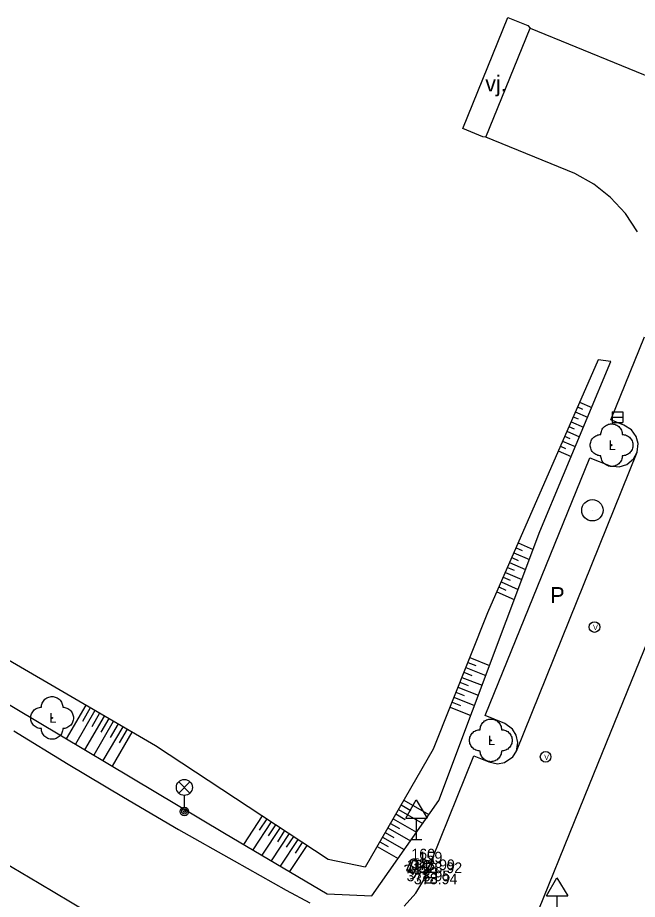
# Model space of a CAD drawing. Extents: x -836568 to -836015, y -1070547 to -1070212.
# Drawn here: x -836423.06 to -836394, y -1070381.44 to -1070340.13 of the extents above; entities that cross this region are included whole.
import ezdxf

# ---------------------------------------------------------------- set-up
doc = ezdxf.new("R2010")
doc.units = 0
for name, color, linetype in [('BodPole_mer', 7, 'Continuous'), ('BodPole_popis', 7, 'Continuous'), ('Doprava_body', 7, 'Continuous'), ('Doprava_hranice', 7, 'Continuous'), ('Doprava_kody', 7, 'Continuous'), ('PovrZnIS_body', 7, 'Continuous'), ('PovrZnIS_hranice', 7, 'Continuous'), ('PovrZnIS_kody', 7, 'Continuous'), ('Rusene_prvky', 7, 'Continuous'), ('Vyskopis_linie', 7, 'Continuous'), ('Zelen_body', 7, 'Continuous')]:
    doc.layers.add(name, color=color, linetype=linetype)

msp = doc.modelspace()

# ---------------------------------------------------------------- linework, layer by layer
at = {"layer": 'BodPole_mer'}
for p, q in [((-836400.07, -1070340.13), (-836400.07, -1070340.13)), ((-836399.14, -1070340.5), (-836399.14, -1070340.5)), ((-836399.02, -1070340.62), (-836399.02, -1070340.62)), ((-836402.18, -1070345.33), (-836402.18, -1070345.33)), ((-836401.25, -1070345.72), (-836401.25, -1070345.72)), ((-836401.11, -1070345.73), (-836401.11, -1070345.73)), ((-836396.94, -1070347.44), (-836396.94, -1070347.44)), ((-836396.04, -1070347.93), (-836396.04, -1070347.93)), ((-836395.26, -1070348.55), (-836395.26, -1070348.55)), ((-836394.55, -1070349.31), (-836394.55, -1070349.31)), ((-836395.84, -1070356.16), (-836395.84, -1070356.16)), ((-836395.25, -1070356.24), (-836395.25, -1070356.24)), ((-836395.25, -1070358.98), (-836395.25, -1070358.98)), ((-836394.93, -1070358.85), (-836394.93, -1070358.85)), ((-836394.63, -1070359.22), (-836394.63, -1070359.22)), ((-836394.27, -1070359.44), (-836394.27, -1070359.44)), ((-836394.05, -1070359.75), (-836394.05, -1070359.75)), ((-836395.21, -1070360.16), (-836395.21, -1070360.16)), ((-836394.01, -1070360.49), (-836394.01, -1070360.49)), ((-836396.23, -1070360.75), (-836396.23, -1070360.75)), ((-836394.49, -1070361.06), (-836394.49, -1070361.06)), ((-836394.18, -1070360.8), (-836394.18, -1070360.8)), ((-836395.27, -1070361.13), (-836395.27, -1070361.13)), ((-836394.85, -1070361.17), (-836394.85, -1070361.17)), ((-836396.11, -1070363.21), (-836396.11, -1070363.21)), ((-836398.57, -1070364.21), (-836398.57, -1070364.21)), ((-836401.02, -1070368.01), (-836401.02, -1070368.01)), ((-836396.01, -1070368.68), (-836396.01, -1070368.68)), ((-836421.44, -1070372.94), (-836421.44, -1070372.94)), ((-836401.14, -1070372.82), (-836401.14, -1070372.82)), ((-836400.21, -1070373.2), (-836400.21, -1070373.2)), ((-836399.86, -1070373.46), (-836399.86, -1070373.46)), ((-836399.68, -1070373.74), (-836399.68, -1070373.74)), ((-836416.6, -1070374.24), (-836416.6, -1070374.24)), ((-836400.87, -1070373.99), (-836400.87, -1070373.99)), ((-836399.6, -1070374.09), (-836399.6, -1070374.09)), ((-836403.57, -1070374.4), (-836403.57, -1070374.4)), ((-836401.66, -1070374.72), (-836401.66, -1070374.72)), ((-836399.66, -1070374.49), (-836399.66, -1070374.49)), ((-836420.69, -1070375.11), (-836420.69, -1070375.11)), ((-836400.97, -1070374.99), (-836400.97, -1070374.99)), ((-836400.56, -1070375.09), (-836400.56, -1070375.09)), ((-836400.23, -1070375.03), (-836400.23, -1070375.03)), ((-836399.84, -1070374.77), (-836399.84, -1070374.77)), ((-836398.3, -1070374.76), (-836398.3, -1070374.76)), ((-836396.26, -1070376.08), (-836396.26, -1070376.08)), ((-836418.1, -1070376.65), (-836418.1, -1070376.65)), ((-836403.31, -1070376.81), (-836403.31, -1070376.81)), ((-836415.24, -1070377.32), (-836415.24, -1070377.32)), ((-836415.51, -1070378.17), (-836415.51, -1070378.17)), ((-836413.35, -1070378.34), (-836413.35, -1070378.34)), ((-836404.36, -1070378.63), (-836404.36, -1070378.63)), ((-836412.9, -1070379.64), (-836412.9, -1070379.64)), ((-836408.49, -1070379.57), (-836408.49, -1070379.57)), ((-836404.6, -1070379.57), (-836404.6, -1070379.57)), ((-836406.76, -1070379.93), (-836406.76, -1070379.93)), ((-836404.82, -1070380.09), (-836404.82, -1070380.09)), ((-836404.26, -1070379.71), (-836404.26, -1070379.71)), ((-836404.48, -1070380.23), (-836404.48, -1070380.23)), ((-836403.68, -1070380.41), (-836403.68, -1070380.41)), ((-836422.05, -1070380.7), (-836422.05, -1070380.7)), ((-836404.01, -1070380.52), (-836404.01, -1070380.52)), ((-836410.46, -1070381.01), (-836410.46, -1070381.01)), ((-836408.55, -1070381.18), (-836408.55, -1070381.18)), ((-836406.45, -1070381.27), (-836406.45, -1070381.27)), ((-836404.38, -1070381.15), (-836404.38, -1070381.15))]:
    msp.add_line(p, q, dxfattribs=at)
at = {"layer": 'Doprava_body'}
for p, q in [((-836404.86, -1070377.63), (-836404.379, -1070376.776)), ((-836404.379, -1070376.776), (-836403.86, -1070377.63)), ((-836404.86, -1070377.63), (-836403.86, -1070377.63)), ((-836404.36, -1070378.63), (-836404.36, -1070377.63)), ((-836404.61, -1070378.63), (-836404.11, -1070378.63)), ((-836398.26, -1070381.28), (-836397.779, -1070380.426)), ((-836397.779, -1070380.426), (-836397.26, -1070381.28)), ((-836398.26, -1070381.28), (-836397.26, -1070381.28)), ((-836397.76, -1070382.28), (-836397.76, -1070381.28))]:
    msp.add_line(p, q, dxfattribs=at)
at = {"layer": 'Doprava_hranice'}
msp.add_line((-836399.66, -1070374.49), (-836394.01, -1070360.49), dxfattribs=at)
for points in [[(-836401.11, -1070345.73), (-836401.25, -1070345.72), (-836402.18, -1070345.33), (-836400.07, -1070340.13), (-836399.14, -1070340.5), (-836399.02, -1070340.62)], [(-836393.99, -1070350.16), (-836394.55, -1070349.31), (-836395.26, -1070348.55), (-836396.04, -1070347.93), (-836396.94, -1070347.44), (-836401.11, -1070345.73), (-836399.02, -1070340.62), (-836392.61, -1070343.24)], [(-836395.27, -1070361.13), (-836394.85, -1070361.17), (-836394.49, -1070361.06), (-836394.18, -1070360.8), (-836394.01, -1070360.49), (-836393.96, -1070360.08), (-836394.05, -1070359.75), (-836394.27, -1070359.44), (-836394.63, -1070359.22), (-836395.25, -1070358.98), (-836393.66, -1070355.09)], [(-836388.58, -1070357.21), (-836396.26, -1070376.08), (-836399.34, -1070383.66)], [(-836404.94, -1070381.76), (-836404.38, -1070381.15), (-836404.01, -1070380.52), (-836401.66, -1070374.72), (-836400.97, -1070374.99), (-836400.56, -1070375.09), (-836400.23, -1070375.03), (-836399.84, -1070374.77), (-836399.66, -1070374.49), (-836399.6, -1070374.09), (-836399.68, -1070373.74), (-836399.86, -1070373.46), (-836400.21, -1070373.2), (-836401.14, -1070372.82), (-836396.23, -1070360.75), (-836395.27, -1070361.13)], [(-836423.24, -1070373.54), (-836420.69, -1070375.11), (-836418.1, -1070376.65), (-836415.51, -1070378.17), (-836412.9, -1070379.64), (-836410.46, -1070381.01), (-836409.36, -1070381.6)], [(-836399.24, -1070392.97), (-836400.17, -1070392.53), (-836400.46, -1070392.39), (-836403.15, -1070391.04), (-836405.83, -1070389.69), (-836408.48, -1070388.3), (-836410.81, -1070387.09), (-836411.14, -1070386.91), (-836411.71, -1070386.58), (-836413.77, -1070385.45), (-836416.56, -1070383.89), (-836418.13, -1070383), (-836419.85, -1070382.01), (-836422.05, -1070380.7), (-836424.17, -1070379.44)]]:
    msp.add_lwpolyline(points, dxfattribs=at)
at = {"layer": 'PovrZnIS_body'}
for p, q in [((-836395.18, -1070358.6), (-836394.68, -1070358.6)), ((-836395.18, -1070358.6), (-836395.18, -1070359.1)), ((-836394.68, -1070358.6), (-836394.68, -1070359.1)), ((-836395.18, -1070358.85), (-836394.68, -1070358.85)), ((-836395.18, -1070359.1), (-836394.68, -1070359.1)), ((-836415.505, -1070376.46), (-836414.975, -1070375.93)), ((-836415.505, -1070375.93), (-836414.975, -1070376.46)), ((-836415.24, -1070377.12), (-836415.24, -1070376.57)), ((-836403.93, -1070380.16), (-836403.43, -1070380.16)), ((-836403.93, -1070380.16), (-836403.93, -1070380.66)), ((-836403.93, -1070380.41), (-836403.43, -1070380.41)), ((-836403.43, -1070380.16), (-836403.43, -1070380.66)), ((-836403.93, -1070380.66), (-836403.43, -1070380.66))]:
    msp.add_line(p, q, dxfattribs=at)
for centre, radius in [((-836396.11, -1070363.21), 0.5), ((-836396.01, -1070368.68), 0.25), ((-836398.3, -1070374.76), 0.25)]:
    msp.add_circle(centre, radius, dxfattribs=at)
for centre, major_axis in [((-836415.24, -1070376.195), (0.375, 0)), ((-836415.24, -1070377.32), (0.2, 0)), ((-836415.236, -1070377.32), (0.125, 0)), ((-836415.236, -1070377.32), (0.05, 0))]:
    msp.add_ellipse(centre, major_axis=major_axis, ratio=0.999998, dxfattribs=at)
at = {"layer": 'PovrZnIS_hranice'}
msp.add_lwpolyline([(-836404.48, -1070380.23), (-836404.26, -1070379.71), (-836404.6, -1070379.57), (-836404.82, -1070380.09), (-836404.48, -1070380.23)], dxfattribs=at)
at = {"layer": 'PovrZnIS_kody'}
for centre, radius, start, end in [((-836404.735, -1070380.146), 0.315, 53.2248, 126.7372), ((-836404.361, -1070379.644), 0.313, 233.1301, 306.8699)]:
    msp.add_arc(centre, radius, start, end, dxfattribs=at)
at = {"layer": 'Rusene_prvky'}
for p, q in [((-836404.72, -1070380.15), (-836404.51, -1070379.61)), ((-836404.28, -1070379.7), (-836404.51, -1070379.61)), ((-836404.51, -1070379.61), (-836404.51, -1070379.61)), ((-836404.49, -1070380.24), (-836404.28, -1070379.7)), ((-836404.28, -1070379.7), (-836404.28, -1070379.7)), ((-836404.72, -1070380.15), (-836404.49, -1070380.24)), ((-836404.72, -1070380.15), (-836404.72, -1070380.15)), ((-836404.49, -1070380.24), (-836404.49, -1070380.24))]:
    msp.add_line(p, q, dxfattribs=at)
for centre, radius, start, end in [((-836404.302, -1070379.67), 0.313, 278.1301, 351.8699), ((-836404.677, -1070380.172), 0.315, 278.2248, 351.7372)]:
    msp.add_arc(centre, radius, start, end, dxfattribs=at)
at = {"layer": 'Vyskopis_linie'}
for p, q in [((-836396.71, -1070358.14), (-836396.14, -1070358.39)), ((-836396.91, -1070358.6), (-836396.34, -1070358.85)), ((-836396.81, -1070358.37), (-836396.58, -1070358.47)), ((-836397.01, -1070358.83), (-836396.77, -1070358.93)), ((-836397.21, -1070359.29), (-836396.97, -1070359.39)), ((-836397.11, -1070359.06), (-836396.53, -1070359.31)), ((-836397.41, -1070359.74), (-836397.17, -1070359.85)), ((-836397.31, -1070359.51), (-836396.72, -1070359.77)), ((-836397.61, -1070360.2), (-836397.37, -1070360.31)), ((-836397.51, -1070359.97), (-836396.91, -1070360.23)), ((-836397.71, -1070360.43), (-836397.11, -1070360.69)), ((-836399.59, -1070364.74), (-836398.89, -1070365.05)), ((-836399.79, -1070365.2), (-836399.06, -1070365.52)), ((-836399.69, -1070364.97), (-836399.4, -1070365.1)), ((-836399.89, -1070365.43), (-836399.59, -1070365.56)), ((-836400.09, -1070365.89), (-836399.78, -1070366.02)), ((-836399.99, -1070365.66), (-836399.24, -1070365.99)), ((-836400.29, -1070366.35), (-836399.97, -1070366.49)), ((-836400.19, -1070366.12), (-836399.42, -1070366.46)), ((-836400.49, -1070366.8), (-836400.16, -1070366.95)), ((-836400.39, -1070366.57), (-836399.59, -1070366.93)), ((-836400.59, -1070367.03), (-836399.77, -1070367.39)), ((-836401.86, -1070370.11), (-836400.93, -1070370.48)), ((-836402.04, -1070370.57), (-836401.1, -1070370.95)), ((-836401.95, -1070370.34), (-836401.57, -1070370.49)), ((-836402.13, -1070370.8), (-836401.76, -1070370.95)), ((-836402.32, -1070371.27), (-836401.94, -1070371.42)), ((-836402.23, -1070371.04), (-836401.28, -1070371.41)), ((-836402.51, -1070371.73), (-836402.12, -1070371.89)), ((-836402.41, -1070371.5), (-836401.46, -1070371.88)), ((-836402.69, -1070372.2), (-836402.3, -1070372.35)), ((-836402.6, -1070371.96), (-836401.63, -1070372.35)), ((-836419.86, -1070372.34), (-836420.78, -1070373.92)), ((-836419.43, -1070372.59), (-836420.35, -1070374.17)), ((-836419.65, -1070372.47), (-836420.01, -1070373.1)), ((-836402.78, -1070372.43), (-836401.81, -1070372.82)), ((-836419, -1070372.85), (-836419.92, -1070374.43)), ((-836419.21, -1070372.72), (-836419.58, -1070373.35)), ((-836418.78, -1070372.97), (-836419.15, -1070373.6)), ((-836418.57, -1070373.1), (-836419.49, -1070374.68)), ((-836418.13, -1070373.35), (-836419.06, -1070374.94)), ((-836418.35, -1070373.22), (-836418.72, -1070373.86)), ((-836417.92, -1070373.47), (-836418.29, -1070374.11)), ((-836417.7, -1070373.6), (-836418.63, -1070375.2)), ((-836404.95, -1070376.79), (-836403.77, -1070377.47)), ((-836405.08, -1070377.01), (-836404.62, -1070377.27)), ((-836411.59, -1070377.53), (-836412.46, -1070378.87)), ((-836405.32, -1070377.44), (-836404.89, -1070377.7)), ((-836405.2, -1070377.23), (-836404.06, -1070377.88)), ((-836411.17, -1070377.81), (-836412.03, -1070379.12)), ((-836411.38, -1070377.67), (-836411.73, -1070378.2)), ((-836410.96, -1070377.95), (-836411.31, -1070378.47)), ((-836405.57, -1070377.88), (-836405.15, -1070378.12)), ((-836405.45, -1070377.66), (-836404.35, -1070378.29)), ((-836410.75, -1070378.08), (-836411.6, -1070379.37)), ((-836410.33, -1070378.36), (-836411.17, -1070379.63)), ((-836410.54, -1070378.22), (-836410.88, -1070378.74)), ((-836405.82, -1070378.31), (-836405.42, -1070378.54)), ((-836405.7, -1070378.09), (-836404.64, -1070378.7)), ((-836409.92, -1070378.63), (-836410.74, -1070379.88)), ((-836410.13, -1070378.5), (-836410.46, -1070379)), ((-836409.71, -1070378.77), (-836410.04, -1070379.27)), ((-836406.07, -1070378.74), (-836405.68, -1070378.97)), ((-836405.95, -1070378.52), (-836404.93, -1070379.11)), ((-836409.5, -1070378.91), (-836410.31, -1070380.14)), ((-836406.2, -1070378.96), (-836405.22, -1070379.52))]:
    msp.add_line(p, q, dxfattribs=at)
for points in [[(-836434.23, -1070354.27), (-836438.23, -1070358.57), (-836440.17, -1070361.78), (-836433.66, -1070365.96), (-836425.36, -1070371.19), (-836413.35, -1070378.34), (-836408.55, -1070381.18), (-836406.45, -1070381.27), (-836403.31, -1070376.81), (-836398.57, -1070364.21), (-836395.25, -1070356.24), (-836395.84, -1070356.16)], [(-836395.84, -1070356.16), (-836401.02, -1070368.01), (-836403.57, -1070374.4), (-836406.76, -1070379.93), (-836408.49, -1070379.57), (-836416.6, -1070374.24), (-836425.3, -1070369.18), (-836431.77, -1070364.85), (-836437.84, -1070361.03), (-836434.23, -1070354.27)]]:
    msp.add_lwpolyline(points, dxfattribs=at)
at = {"layer": 'Zelen_body'}
for p, q in [((-836395.21, -1070360.16), (-836395.21, -1070360.16)), ((-836421.44, -1070372.94), (-836421.44, -1070372.94)), ((-836400.87, -1070373.99), (-836400.87, -1070373.99))]:
    msp.add_line(p, q, dxfattribs=at)
for points in [[(-836395.71, -1070359.66), (-836395.708, -1070359.612), (-836395.7, -1070359.563), (-836395.688, -1070359.513), (-836395.67, -1070359.464), (-836395.646, -1070359.415), (-836395.617, -1070359.369), (-836395.583, -1070359.326), (-836395.544, -1070359.287), (-836395.501, -1070359.253), (-836395.455, -1070359.224), (-836395.406, -1070359.2), (-836395.357, -1070359.182), (-836395.307, -1070359.17), (-836395.258, -1070359.162), (-836395.21, -1070359.16), (-836395.162, -1070359.162), (-836395.113, -1070359.17), (-836395.063, -1070359.182), (-836395.014, -1070359.2), (-836394.965, -1070359.224), (-836394.919, -1070359.253), (-836394.876, -1070359.287), (-836394.837, -1070359.326), (-836394.803, -1070359.369), (-836394.774, -1070359.415), (-836394.75, -1070359.464), (-836394.732, -1070359.513), (-836394.72, -1070359.563), (-836394.712, -1070359.612), (-836394.71, -1070359.66)], [(-836395.71, -1070360.66), (-836395.758, -1070360.658), (-836395.807, -1070360.65), (-836395.857, -1070360.638), (-836395.906, -1070360.62), (-836395.955, -1070360.596), (-836396.001, -1070360.567), (-836396.044, -1070360.533), (-836396.083, -1070360.494), (-836396.117, -1070360.451), (-836396.146, -1070360.405), (-836396.17, -1070360.356), (-836396.188, -1070360.307), (-836396.2, -1070360.257), (-836396.208, -1070360.208), (-836396.21, -1070360.16), (-836396.208, -1070360.112), (-836396.2, -1070360.063), (-836396.188, -1070360.013), (-836396.17, -1070359.964), (-836396.146, -1070359.915), (-836396.117, -1070359.869), (-836396.083, -1070359.826), (-836396.044, -1070359.787), (-836396.001, -1070359.753), (-836395.955, -1070359.724), (-836395.906, -1070359.7), (-836395.857, -1070359.682), (-836395.807, -1070359.67), (-836395.758, -1070359.662), (-836395.71, -1070359.66)], [(-836394.71, -1070359.66), (-836394.662, -1070359.662), (-836394.613, -1070359.67), (-836394.563, -1070359.682), (-836394.514, -1070359.7), (-836394.465, -1070359.724), (-836394.419, -1070359.753), (-836394.376, -1070359.787), (-836394.337, -1070359.826), (-836394.303, -1070359.869), (-836394.274, -1070359.915), (-836394.25, -1070359.964), (-836394.232, -1070360.013), (-836394.22, -1070360.063), (-836394.212, -1070360.112), (-836394.21, -1070360.16), (-836394.212, -1070360.208), (-836394.22, -1070360.257), (-836394.232, -1070360.307), (-836394.25, -1070360.356), (-836394.274, -1070360.405), (-836394.303, -1070360.451), (-836394.337, -1070360.494), (-836394.376, -1070360.533), (-836394.419, -1070360.567), (-836394.465, -1070360.596), (-836394.514, -1070360.62), (-836394.563, -1070360.638), (-836394.613, -1070360.65), (-836394.662, -1070360.658), (-836394.71, -1070360.66)], [(-836394.71, -1070360.66), (-836394.712, -1070360.708), (-836394.72, -1070360.757), (-836394.732, -1070360.807), (-836394.75, -1070360.856), (-836394.774, -1070360.905), (-836394.803, -1070360.951), (-836394.837, -1070360.994), (-836394.876, -1070361.033), (-836394.919, -1070361.067), (-836394.965, -1070361.096), (-836395.014, -1070361.12), (-836395.063, -1070361.138), (-836395.113, -1070361.15), (-836395.162, -1070361.158), (-836395.21, -1070361.16), (-836395.258, -1070361.158), (-836395.307, -1070361.15), (-836395.357, -1070361.138), (-836395.406, -1070361.12), (-836395.455, -1070361.096), (-836395.501, -1070361.067), (-836395.544, -1070361.033), (-836395.583, -1070360.994), (-836395.617, -1070360.951), (-836395.646, -1070360.905), (-836395.67, -1070360.856), (-836395.688, -1070360.807), (-836395.7, -1070360.757), (-836395.708, -1070360.708), (-836395.71, -1070360.66)], [(-836421.94, -1070372.44), (-836421.938, -1070372.392), (-836421.93, -1070372.343), (-836421.918, -1070372.293), (-836421.9, -1070372.244), (-836421.876, -1070372.195), (-836421.847, -1070372.149), (-836421.813, -1070372.106), (-836421.774, -1070372.067), (-836421.731, -1070372.033), (-836421.685, -1070372.004), (-836421.636, -1070371.98), (-836421.587, -1070371.962), (-836421.537, -1070371.95), (-836421.488, -1070371.942), (-836421.44, -1070371.94), (-836421.392, -1070371.942), (-836421.343, -1070371.95), (-836421.293, -1070371.962), (-836421.244, -1070371.98), (-836421.195, -1070372.004), (-836421.149, -1070372.033), (-836421.106, -1070372.067), (-836421.067, -1070372.106), (-836421.033, -1070372.149), (-836421.004, -1070372.195), (-836420.98, -1070372.244), (-836420.962, -1070372.293), (-836420.95, -1070372.343), (-836420.942, -1070372.392), (-836420.94, -1070372.44)], [(-836421.94, -1070373.44), (-836421.988, -1070373.438), (-836422.037, -1070373.43), (-836422.087, -1070373.418), (-836422.136, -1070373.4), (-836422.185, -1070373.376), (-836422.231, -1070373.347), (-836422.274, -1070373.313), (-836422.313, -1070373.274), (-836422.347, -1070373.231), (-836422.376, -1070373.185), (-836422.4, -1070373.136), (-836422.418, -1070373.087), (-836422.43, -1070373.037), (-836422.438, -1070372.988), (-836422.44, -1070372.94), (-836422.438, -1070372.892), (-836422.43, -1070372.843), (-836422.418, -1070372.793), (-836422.4, -1070372.744), (-836422.376, -1070372.695), (-836422.347, -1070372.649), (-836422.313, -1070372.606), (-836422.274, -1070372.567), (-836422.231, -1070372.533), (-836422.185, -1070372.504), (-836422.136, -1070372.48), (-836422.087, -1070372.462), (-836422.037, -1070372.45), (-836421.988, -1070372.442), (-836421.94, -1070372.44)], [(-836420.94, -1070372.44), (-836420.892, -1070372.442), (-836420.843, -1070372.45), (-836420.793, -1070372.462), (-836420.744, -1070372.48), (-836420.695, -1070372.504), (-836420.649, -1070372.533), (-836420.606, -1070372.567), (-836420.567, -1070372.606), (-836420.533, -1070372.649), (-836420.504, -1070372.695), (-836420.48, -1070372.744), (-836420.462, -1070372.793), (-836420.45, -1070372.843), (-836420.442, -1070372.892), (-836420.44, -1070372.94), (-836420.442, -1070372.988), (-836420.45, -1070373.037), (-836420.462, -1070373.087), (-836420.48, -1070373.136), (-836420.504, -1070373.185), (-836420.533, -1070373.231), (-836420.567, -1070373.274), (-836420.606, -1070373.313), (-836420.649, -1070373.347), (-836420.695, -1070373.376), (-836420.744, -1070373.4), (-836420.793, -1070373.418), (-836420.843, -1070373.43), (-836420.892, -1070373.438), (-836420.94, -1070373.44)], [(-836401.37, -1070373.49), (-836401.368, -1070373.442), (-836401.36, -1070373.393), (-836401.348, -1070373.343), (-836401.33, -1070373.294), (-836401.306, -1070373.245), (-836401.277, -1070373.199), (-836401.243, -1070373.156), (-836401.204, -1070373.117), (-836401.161, -1070373.083), (-836401.115, -1070373.054), (-836401.066, -1070373.03), (-836401.017, -1070373.012), (-836400.967, -1070373), (-836400.918, -1070372.992), (-836400.87, -1070372.99), (-836400.822, -1070372.992), (-836400.773, -1070373), (-836400.723, -1070373.012), (-836400.674, -1070373.03), (-836400.625, -1070373.054), (-836400.579, -1070373.083), (-836400.536, -1070373.117), (-836400.497, -1070373.156), (-836400.463, -1070373.199), (-836400.434, -1070373.245), (-836400.41, -1070373.294), (-836400.392, -1070373.343), (-836400.38, -1070373.393), (-836400.372, -1070373.442), (-836400.37, -1070373.49)], [(-836420.94, -1070373.44), (-836420.942, -1070373.488), (-836420.95, -1070373.537), (-836420.962, -1070373.587), (-836420.98, -1070373.636), (-836421.004, -1070373.685), (-836421.033, -1070373.731), (-836421.067, -1070373.774), (-836421.106, -1070373.813), (-836421.149, -1070373.847), (-836421.195, -1070373.876), (-836421.244, -1070373.9), (-836421.293, -1070373.918), (-836421.343, -1070373.93), (-836421.392, -1070373.938), (-836421.44, -1070373.94), (-836421.488, -1070373.938), (-836421.537, -1070373.93), (-836421.587, -1070373.918), (-836421.636, -1070373.9), (-836421.685, -1070373.876), (-836421.731, -1070373.847), (-836421.774, -1070373.813), (-836421.813, -1070373.774), (-836421.847, -1070373.731), (-836421.876, -1070373.685), (-836421.9, -1070373.636), (-836421.918, -1070373.587), (-836421.93, -1070373.537), (-836421.938, -1070373.488), (-836421.94, -1070373.44)], [(-836401.37, -1070374.49), (-836401.418, -1070374.488), (-836401.467, -1070374.48), (-836401.517, -1070374.468), (-836401.566, -1070374.45), (-836401.615, -1070374.426), (-836401.661, -1070374.397), (-836401.704, -1070374.363), (-836401.743, -1070374.324), (-836401.777, -1070374.281), (-836401.806, -1070374.235), (-836401.83, -1070374.186), (-836401.848, -1070374.137), (-836401.86, -1070374.087), (-836401.868, -1070374.038), (-836401.87, -1070373.99), (-836401.868, -1070373.942), (-836401.86, -1070373.893), (-836401.848, -1070373.843), (-836401.83, -1070373.794), (-836401.806, -1070373.745), (-836401.777, -1070373.699), (-836401.743, -1070373.656), (-836401.704, -1070373.617), (-836401.661, -1070373.583), (-836401.615, -1070373.554), (-836401.566, -1070373.53), (-836401.517, -1070373.512), (-836401.467, -1070373.5), (-836401.418, -1070373.492), (-836401.37, -1070373.49)], [(-836400.37, -1070373.49), (-836400.322, -1070373.492), (-836400.273, -1070373.5), (-836400.223, -1070373.512), (-836400.174, -1070373.53), (-836400.125, -1070373.554), (-836400.079, -1070373.583), (-836400.036, -1070373.617), (-836399.997, -1070373.656), (-836399.963, -1070373.699), (-836399.934, -1070373.745), (-836399.91, -1070373.794), (-836399.892, -1070373.843), (-836399.88, -1070373.893), (-836399.872, -1070373.942), (-836399.87, -1070373.99), (-836399.872, -1070374.038), (-836399.88, -1070374.087), (-836399.892, -1070374.137), (-836399.91, -1070374.186), (-836399.934, -1070374.235), (-836399.963, -1070374.281), (-836399.997, -1070374.324), (-836400.036, -1070374.363), (-836400.079, -1070374.397), (-836400.125, -1070374.426), (-836400.174, -1070374.45), (-836400.223, -1070374.468), (-836400.273, -1070374.48), (-836400.322, -1070374.488), (-836400.37, -1070374.49)], [(-836400.37, -1070374.49), (-836400.372, -1070374.538), (-836400.38, -1070374.587), (-836400.392, -1070374.637), (-836400.41, -1070374.686), (-836400.434, -1070374.735), (-836400.463, -1070374.781), (-836400.497, -1070374.824), (-836400.536, -1070374.863), (-836400.579, -1070374.897), (-836400.625, -1070374.926), (-836400.674, -1070374.95), (-836400.723, -1070374.968), (-836400.773, -1070374.98), (-836400.822, -1070374.988), (-836400.87, -1070374.99), (-836400.918, -1070374.988), (-836400.967, -1070374.98), (-836401.017, -1070374.968), (-836401.066, -1070374.95), (-836401.115, -1070374.926), (-836401.161, -1070374.897), (-836401.204, -1070374.863), (-836401.243, -1070374.824), (-836401.277, -1070374.781), (-836401.306, -1070374.735), (-836401.33, -1070374.686), (-836401.348, -1070374.637), (-836401.36, -1070374.587), (-836401.368, -1070374.538), (-836401.37, -1070374.49)]]:
    msp.add_lwpolyline(points, dxfattribs=at)
for centre in [(-836395.21, -1070360.16), (-836421.44, -1070372.94), (-836400.87, -1070373.99)]:
    msp.add_ellipse(centre, major_axis=(0.025, 0), ratio=0.999997, dxfattribs=at)

# ---------------------------------------------------------------- texts
at = {"layer": 'BodPole_popis'}
for s, p in [('160', (-836404.6, -1070379.57)), ('159', (-836404.26, -1070379.71)), ('161', (-836404.82, -1070380.09)), ('378.99', (-836404.6, -1070380.07)), ('378.95', (-836404.82, -1070380.59)), ('158', (-836404.48, -1070380.23)), ('378.92', (-836404.26, -1070380.21)), ('378.94', (-836404.48, -1070380.73))]:
    msp.add_text(s, height=0.5, dxfattribs=at).set_placement(p)
at = {"layer": 'Doprava_kody'}
for s, p in [('vj.', (-836401.13, -1070343.59)), ('P', (-836398.08, -1070367.56))]:
    msp.add_text(s, height=0.75, dxfattribs=at).set_placement(p)
at = {"layer": 'PovrZnIS_body'}
for p in [(-836396.081, -1070368.823), (-836398.371, -1070374.903)]:
    msp.add_text('V', height=0.25, dxfattribs=at).set_placement(p)
at = {"layer": 'Zelen_body'}
for p in [(-836395.341, -1070360.385), (-836421.571, -1070373.165), (-836401.001, -1070374.215)]:
    msp.add_text('L', height=0.45, dxfattribs=at).set_placement(p)

doc.saveas('drawing.dxf')
